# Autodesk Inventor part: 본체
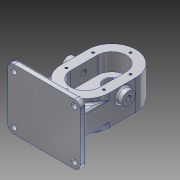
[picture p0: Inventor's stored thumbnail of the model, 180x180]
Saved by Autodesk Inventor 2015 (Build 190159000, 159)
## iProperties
Created: 2020-09
Part Number: 본체
Material: 알루미늄 6061
Document SubType Name: Modeling
Designer: Administrator
Density: 2.7 g/cm^3
Appearance: 알루미늄 - 평지
Mass: 1440.46 g
Surface Area: 785.636 cm^2
Volume: 533.505 cm^3
Author: Administrator
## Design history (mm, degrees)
sketch "스케치1"
  geometry: L1 (0, 0)-(0, -44); L2 (-40, 0)-(-40, -44); L3 (40, -44)-(40, 0); A1 r 40 centre (0, 0) between (40, 0) and (-40, 0); A2 r 40 centre (0, -44) between (-40, -44) and (40, -44); 1 further point
  constraints: 8 end point, 4 point on circle, 4 tangent, 2 centre point, 1 midpoint, 1 parallel, 1 vertical
  dimensions: "d0" = 44 distance of L1.start L1.end; "d1" = 80 diameter of A2
extrude "돌출1" new body sketch "스케치1" distance "d2" = 53; taper "d3" = 0 deg
sketch "스케치2"
  geometry: L1 (0, 0)-(0, -44); L2 (-24, 0)-(-24, -44); L3 (24, -44)-(24, 0); A1 r 24 centre (0, 0) between (24, 0) and (-24, 0); A2 r 24 centre (0, -44) between (-24, -44) and (24, -44); 1 further point
  constraints: 8 end point, 4 point on circle, 4 tangent, 2 centre point, 1 midpoint, 1 parallel, 1 vertical
  dimensions: "d4" = 44 distance of L1.start L1.end; "d5" = 48 diameter of A2
extrude "돌출2" cut sketch "스케치2" distance "d6" = 29; taper "d7" = 0 deg
sketch "스케치3"
  geometry: L1 (-24, -44)-(-24, 0) reference; L2 (24, 0)-(24, -44) reference; C1 r 12.5 at (0, 0); C2 r 12.5 at (0, -44); A1 r 24 centre (0, -44) between (-24, -44) and (24, -44) reference; A2 r 24 centre (0, 0) between (24, 0) and (-24, 0) reference; 1 further point
  constraints: 2 centre point, 2 coincident
  dimensions: "d8" = 25 diameter of C1; "d9" = 25 diameter of C2
extrude "돌출3" cut sketch "스케치3" distance "d10" = 15; taper "d11" = 0 deg
sketch "스케치4"
  geometry: L1 (40, 0)-(40, -44) reference; L2 (-40, -44)-(-40, 0) reference; C1 r 19 at (0, 0); A1 r 40 centre (0, 0) between (40, 0) and (-40, 0) reference; A2 r 40 centre (0, -44) between (-40, -44) and (40, -44) reference; 1 further point
  constraints: 1 centre point, 1 coincident
  dimensions: "d12" = 38 diameter of C1
extrude "돌출4" join sketch "스케치4" distance "d13" = 17; taper "d14" = 0 deg
sketch "스케치5"
  geometry: C1 r 19 at (0, 0) reference; C2 r 14 at (0, 0); 1 further point
  constraints: 1 centre point, 1 coincident
  dimensions: "d15" = 28 diameter of C2
extrude "돌출5" cut sketch "스케치5" distance "d16" = 7.3; taper "d17" = 0 deg
sketch "스케치6"
  geometry: C1 r 14 at (0, 0) reference; C2 r 8.5 at (0, 0); 1 further point
  constraints: 1 centre point, 1 coincident
  dimensions: "d18" = 17 diameter of C2
extrude "돌출6" cut sketch "스케치6" stored distance "d19" = 7.3; taper "d20" = 0 deg
chamfer "모따기1" distance "d21" = 0.7; stored, may be unused: second distance "d22" = 2, angle "d23" = 30 deg
chamfer "모따기2" distance "d24" = 1; stored, may be unused: second distance "d25" = 2, angle "d26" = 30 deg
sketch "스케치7"
  geometry: L1 (-24, -44)-(-24, 0) reference; L2 (24, 0)-(24, -44) reference; L3 (-40, 0)-(-40, -44) reference; L4 (40, -44)-(40, 0) reference; A1 r 24 centre (0, -44) between (-24, -44) and (24, -44) reference; A2 r 24 centre (0, 0) between (24, 0) and (-24, 0) reference; A3 r 40 centre (0, -44) between (-40, -44) and (40, -44) reference; A4 r 40 centre (0, 0) between (40, 0) and (-40, 0) reference; A5 r 31 centre (0, 0) between (31, 0) and (0, 31); A6 r 31 centre (0, -44) between (-31, -44) and (31, -44); 3 further points
  constraints: 6 point on circle, 2 centre point, 2 coincident
  dimensions: "d28" = 62 diameter of A5; "d29" = 62 diameter of A6; "d30" = 9 distance from line of A5.start L4; "d31" = 9 distance from line of A6.end L4; "d32" = 40 distance from line of A5.end L4; "d33" = 40 distance from line of point (0, -75) L4; "d34" = 71 distance from line of point (-31, 0) L4; "d35" = 71 distance from line of A6.start L4
hole "구멍1" sketch "스케치7" at (31, 0), (0, 31), (-31, 0), (-31, -44), (31, -44), (0, -75) diameter "d36" = 4.134; stored, may be unused: countersink angle "d40" = 90 deg, drill point angle "d42" = 118 deg; dims "d37" = 10, "d38" = 4, "d39" = 2, "d41" = 12
sketch "스케치8"
  geometry: L1 (-53, 0)-(-53, 44) reference; L2 (-53, 22)-(-39, 22); C1 r 11 at (-39, 22); 1 further point
  constraints: 2 end point, 1 centre point, 1 coincident, 1 horizontal, 1 midpoint
  dimensions: "d43" = 14 distance of L2.start L2.end; "d44" = 22 diameter of C1
extrude "돌출7" join sketch "스케치8" distance "d45" = 10; taper "d46" = 0 deg
sketch "스케치9"
  geometry: L1 (53, 44)-(53, 0) reference; L2 (53, 22)-(39, 22); C1 r 11 at (39, 22); 1 further point
  constraints: 2 end point, 1 centre point, 1 coincident, 1 horizontal, 1 midpoint
  dimensions: "d47" = 14 distance of L2.start L2.end; "d48" = 22 diameter of C1
extrude "돌출8" join sketch "스케치9" distance "d49" = 10; taper "d50" = 0 deg
sketch "스케치10"
  geometry: C1 r 11 at (0, 0) reference; 2 further points
  constraints: 1 coincident
hole "구멍2" sketch "스케치10" at (0, 0) diameter "d51" = 8.376; stored, may be unused: countersink angle "d55" = 90 deg, drill point angle "d57" = 0 deg; dims "d52" = 30, "d53" = 4, "d54" = 2, "d56" = 40
sketch "스케치11"
  geometry: C1 r 11 at (0, 0) reference; 2 further points
  constraints: 1 coincident
hole "구멍3" sketch "스케치11" at (0, 0) diameter "d58" = 8.376; stored, may be unused: countersink angle "d62" = 90 deg, drill point angle "d64" = 0 deg; dims "d59" = 30, "d60" = 4, "d61" = 2, "d63" = 40
node "작업 평면1"
sketch "스케치12"
  geometry: L1 (-19, -17)-(19, -17) reference; L2 (0, -17)-(60, -17); L3 (60, -17)-(60, 83); L4 (60, 83)-(-60, 83); L5 (-60, 83)-(-60, -17); L6 (-60, -17)-(0, -17); 1 further point
  constraints: 10 end point, 3 perpendicular, 1 collinear, 1 horizontal, 1 midpoint, 1 point on line
  dimensions: "d66" = 60 distance of L2.start L2.end; "d67" = 100 distance of L2.end L3.end; "d68" = 120 distance of L3.end L4.end
extrude "돌출9" join sketch "스케치12" distance "d69" = 10; taper "d70" = 0 deg
node "작업 평면2"
sketch "스케치13"
  geometry: L1 (84, 68)-(84, 112) reference; L2 (36, 112)-(36, 68) reference; L3 (100, 112)-(100, 68) reference; L4 (20, 68)-(20, 112) reference; L5 (20, 68)-(20, 10); L6 (0, 10)-(120, 10) reference; L7 (20, 68)-(20, 112) reference; L8 (100, 68)-(100, 10); L9 (100, 10)-(20, 10); C1 r 2.067 at (29, 68) reference; C2 r 2.067 at (91, 112) reference; C3 r 2.067 at (29, 112) reference; C4 r 2.067 at (60, 143) reference; C5 r 2.067 at (91, 68) reference; C6 r 2.067 at (60, 37) reference; A1 r 24 centre (60, 68) between (36, 68) and (84, 68) reference; A2 r 24 centre (60, 112) between (84, 112) and (36, 112) reference; A3 r 40 centre (60, 68) between (20, 68) and (100, 68) reference; A4 r 40 centre (60, 112) between (100, 112) and (20, 112) reference; A5 r 40 centre (60, 68) between (20, 68) and (100, 68) reference; A6 r 40.121 centre (60, 71.116) between (20, 68) and (100, 68); 1 further point
  constraints: 6 end point, 2 collinear, 2 point on circle, 2 point on line, 1 centre point, 1 perpendicular, 1 tangent
  dimensions: "d72" = 40.12121 radius of A6
extrude "돌출10" join sketch "스케치13" distance "d73" = 37; taper "d74" = 0 deg
sketch "스케치14"
  geometry: L1 (-60, 17)-(-60, -83) reference; L2 (-60, -83)-(60, -83) reference; 2 further points
  constraints: 1 other
  dimensions: "d75" = 60 distance from line of L1 point (0, -71); "d76" = 12 distance from line of L2 point (0, -71)
feature "엠보싱1" sketch "스케치14" dims "d0" = 44, "d1" = 80, "d77" = 0.5, "d78" = 0
fillet "모깎기2" dims "d79" = 3
fillet "모깎기3" dims "d80" = 3
fillet "모깎기4" dims "d81" = 3
fillet "모깎기5" dims "d82" = 3
fillet "모깎기6" dims "d83" = 3
fillet "모깎기7" dims "d84" = 0.5
fillet "모깎기8" dims "d85" = 3
fillet "모깎기9" dims "d86" = 3
fillet "모깎기10" dims "d87" = 10
fillet "모깎기11" dims "d88" = 3
sketch "스케치15"
  geometry: A1 r 7 centre (50, -73) between (50, -80) and (57, -73) reference; A2 r 7 centre (50, 7) between (57, 7) and (50, 14) reference; A3 r 7 centre (-50, 7) between (-50, 14) and (-57, 7) reference; A4 r 7 centre (-50, -73) between (-57, -73) and (-50, -80) reference; 5 further points
  constraints: 4 coincident
hole "구멍4" sketch "스케치15" at (50, 7), (-50, 7), (-50, -73), (50, -73) diameter "d89" = 9; stored, may be unused: countersink angle "d93" = 90 deg, drill point angle "d95" = 0 deg; dims "d90" = 6, "d91" = 4, "d92" = 2, "d94" = 11
node "솔리드1"
node "투영된 루프1"
node "투영된 루프2"
node "투영된 루프3"
node "투영된 루프4"
node "투영된 루프5"
node "투영된 루프6"
node "투영된 루프7"
other parameters: "d65" = -112, "d71" = -62
